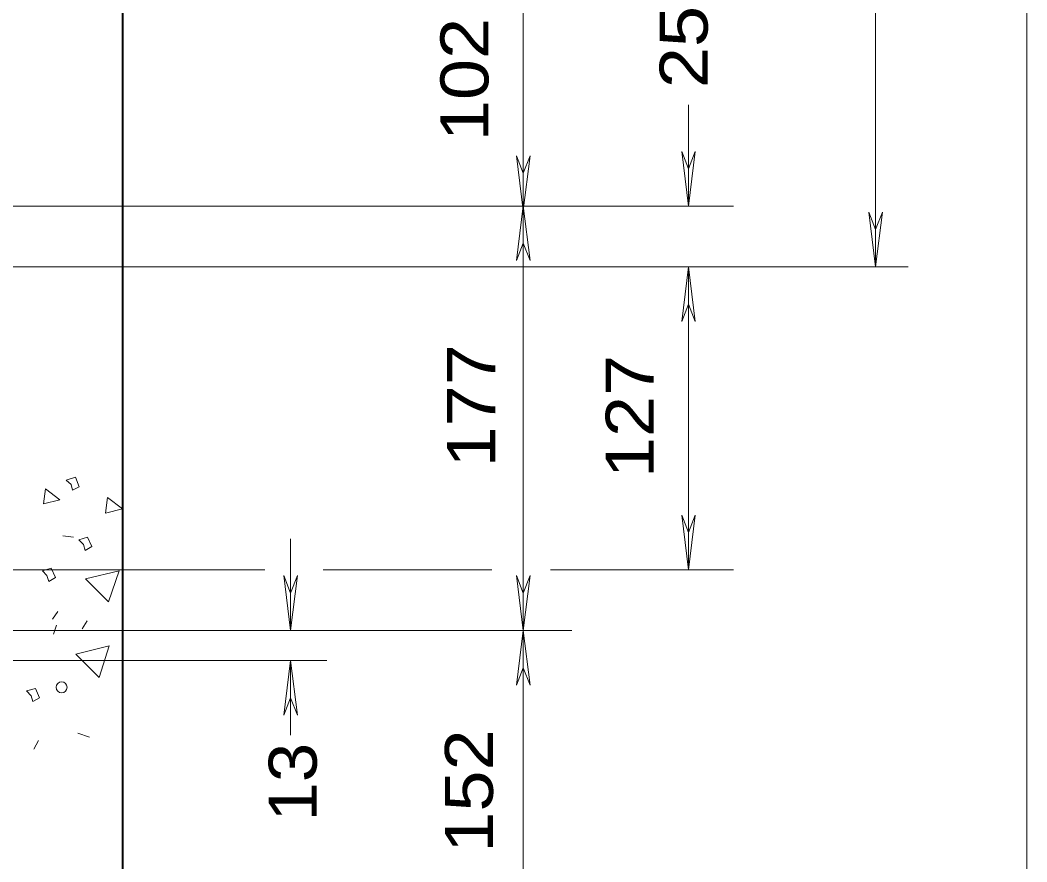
# Model space of a CAD drawing. Extents: x 312583 to 312854, y 144419 to 144597.
# Drawn here: x 312724.13 to 312740.06, y 144453.7 to 144467.02 of the extents above; entities that cross this region are included whole.
import ezdxf

# ---------------------------------------------------------------- set-up
doc = ezdxf.new("R2010")
doc.units = 0
doc.header["$LTSCALE"] = 0.3
doc.layers.add('1', color=7, linetype='Continuous', lineweight=25)
doc.layers.add('2', color=7, linetype='Continuous', lineweight=13)

msp = doc.modelspace()

# ---------------------------------------------------------------- linework, layer by layer
at = {"layer": '1', "lineweight": 40}
msp.add_line((312725.751, 144497.14), (312725.751, 144451.6154), dxfattribs=at)
at = {"layer": '2'}
for p, q in [((312737.665, 144463.1154), (312737.665, 144497.6154)), ((312740.057, 144451.6154), (312740.057, 144497.6154)), ((312732.0914, 144467.907), (312732.0914, 144463.1154)), ((312734.7057, 144464.0737), (312734.7057, 144465.676)), ((312734.5984, 144464.94), (312734.7057, 144464.664)), ((312734.7057, 144464.0737), (312734.5984, 144464.94)), ((312734.813, 144464.94), (312734.7057, 144464.664)), ((312734.7057, 144464.0737), (312734.813, 144464.94)), ((312731.984, 144464.871), (312732.0914, 144464.595)), ((312732.0914, 144464.0047), (312731.984, 144464.871)), ((312732.1987, 144464.871), (312732.0914, 144464.595)), ((312732.0914, 144464.0047), (312732.1987, 144464.871)), ((312721.657, 144464.0737), (312733.203, 144464.0737)), ((312732.0914, 144464.0814), (312731.984, 144463.215)), ((312732.0914, 144464.0814), (312732.1987, 144463.215)), ((312733.203, 144464.0737), (312735.4187, 144464.0737)), ((312737.5577, 144463.9817), (312737.665, 144463.7057)), ((312737.665, 144463.1154), (312737.5577, 144463.9817)), ((312737.7724, 144463.9817), (312737.665, 144463.7057)), ((312737.665, 144463.1154), (312737.7724, 144463.9817)), ((312731.984, 144463.215), (312732.0914, 144463.491)), ((312732.1987, 144463.215), (312732.0914, 144463.491)), ((312723.3667, 144463.1154), (312738.1787, 144463.1154)), ((312734.7057, 144463.1154), (312734.5984, 144462.249)), ((312734.7057, 144458.3237), (312734.7057, 144463.1154)), ((312734.7057, 144463.1154), (312734.813, 144462.249)), ((312734.5984, 144462.249), (312734.7057, 144462.525)), ((312734.813, 144462.249), (312734.7057, 144462.525)), ((312734.5984, 144459.19), (312734.7057, 144458.914)), ((312734.7057, 144458.3237), (312734.5984, 144459.19)), ((312734.813, 144459.19), (312734.7057, 144458.914)), ((312734.7057, 144458.3237), (312734.813, 144459.19)), ((312724.9767, 144458.8374), (312724.808, 144458.8604)), ((312728.4114, 144457.3654), (312728.4114, 144458.8144)), ((312723.5124, 144458.3237), (312728.005, 144458.3237)), ((312728.925, 144458.3237), (312731.593, 144458.3237)), ((312732.5207, 144458.3237), (312735.4187, 144458.3237)), ((312728.304, 144458.2317), (312728.4114, 144457.9557)), ((312728.4114, 144457.3654), (312728.304, 144458.2317)), ((312728.5187, 144458.2317), (312728.4114, 144457.9557)), ((312728.4114, 144457.3654), (312728.5187, 144458.2317)), ((312731.984, 144458.2317), (312732.0914, 144457.9557)), ((312732.0914, 144457.3654), (312731.984, 144458.2317)), ((312732.1987, 144458.2317), (312732.0914, 144457.9557)), ((312732.0914, 144457.3654), (312732.1987, 144458.2317)), ((312724.7314, 144457.6644), (312724.647, 144457.5417)), ((312724.7084, 144457.4497), (312724.6624, 144457.304)), ((312725.1914, 144457.5187), (312725.1147, 144457.3884)), ((312719.9244, 144457.3654), (312732.858, 144457.3654)), ((312732.0914, 144457.3654), (312731.984, 144456.499)), ((312732.0914, 144457.3654), (312732.1987, 144456.499)), ((312713.1087, 144456.89), (312728.9864, 144456.89)), ((312728.4114, 144456.89), (312728.304, 144456.0237)), ((312728.4114, 144455.7094), (312728.4114, 144456.89)), ((312728.4114, 144456.89), (312728.5187, 144456.0237)), ((312731.984, 144456.499), (312732.0914, 144456.775)), ((312732.1987, 144456.499), (312732.0914, 144456.775)), ((312728.304, 144456.0237), (312728.4114, 144456.2997)), ((312728.5187, 144456.0237), (312728.4114, 144456.2997)), ((312725.2297, 144455.6787), (312725.0457, 144455.74)), ((312724.4247, 144455.625), (312724.348, 144455.487))]:
    msp.add_line(p, q, dxfattribs=at)
msp.add_lwpolyline([(312732.0914, 144451.6154), (312732.0914, 144457.3654), (312732.0914, 144463.1154)], dxfattribs=at)
for points in [[(312724.9384, 144459.673), (312724.9614, 144459.581), (312725.0687, 144459.6347), (312725.0074, 144459.788), (312724.8617, 144459.742)], [(312724.532, 144459.604), (312724.5014, 144459.3664), (312724.762, 144459.4277)], [(312725.5134, 144459.466), (312725.4827, 144459.2207), (312725.751, 144459.2897)], [(312725.1377, 144458.7224), (312725.1607, 144458.6304), (312725.268, 144458.6917), (312725.199, 144458.8374), (312725.061, 144458.799)], [(312724.555, 144458.2317), (312724.5857, 144458.1397), (312724.693, 144458.201), (312724.624, 144458.3467), (312724.486, 144458.3084)], [(312725.1684, 144458.178), (312725.5287, 144457.8177), (312725.6974, 144458.3084)], [(312725.015, 144456.9897), (312725.383, 144456.6217), (312725.544, 144457.12)], [(312724.3097, 144456.3304), (312724.3327, 144456.2384), (312724.44, 144456.2997), (312724.3787, 144456.4454), (312724.233, 144456.407)]]:
    msp.add_lwpolyline(points, close=True, dxfattribs=at)
msp.add_circle((312724.7885, 144456.4644), 0.0865, dxfattribs=at)

# ---------------------------------------------------------------- texts
for s, width, p in [('25 ', 1.15, (312735.0088, 144465.9414)), ('102 ', 1.15, (312731.541, 144465.1036)), ('177 ', 1.15, (312731.6472, 144459.9424)), ('127 ', 1.15, (312734.1553, 144459.7735)), ('152 ', 1.15, (312731.6118, 144453.8491)), ('13 ', 1.1, (312728.8248, 144454.3433))]:
    msp.add_text(s, height=0.76, rotation=90, dxfattribs=dict(at, width=width)).set_placement(p)

doc.saveas('drawing.dxf')
